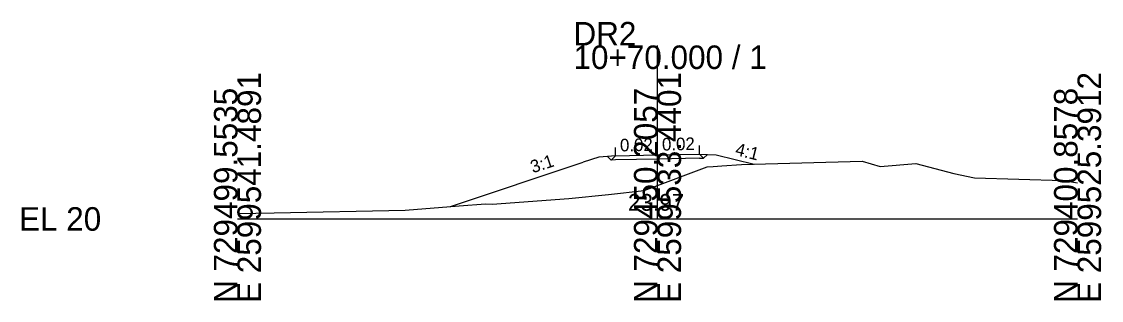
# Model space of a CAD drawing. Extents: x -26 to 1162, y -10 to 9515.
# Drawn here: x -25.7 to 102.8, y 3490.3 to 3523.5 of the extents above; entities that cross this region are included whole.
import ezdxf

# ---------------------------------------------------------------- set-up
doc = ezdxf.new("R2010")
doc.units = 0
for name, color, linetype in [('Exist Cross Section Cell', 7, 'Continuous'), ('Exist XS Center Line Elevation Label', 7, 'Continuous'), ('Exist XS Ground Line', 7, 'Continuous'), ('Prop XS Dump Level', 7, 'Continuous'), ('Prop XS EOT Tick Mark', 7, 'Continuous'), ('Prop XS Finish Grade', 7, 'Continuous'), ('Prop XS Finish Grade Earthwork', 7, 'Continuous'), ('Prop XS Finish Grade Pavement', 7, 'Continuous'), ('Prop XS Pvmt Edge Slope', 7, 'Continuous'), ('Prop XS SE Text', 7, 'Continuous'), ('Prop XS Side Slope Text', 7, 'Continuous'), ('Prop XS Subgrade Earthwork', 7, 'Continuous')]:
    doc.layers.add(name, color=color, linetype=linetype)

msp = doc.modelspace()

# ---------------------------------------------------------------- linework, layer by layer
at = {"layer": 'Exist Cross Section Cell'}
for p, q in [((50, 3500), (50, 3520.64)), ((0, 3500), (50, 3500)), ((50, 3500), (100, 3500))]:
    msp.add_line(p, q, dxfattribs=at)
at = {"layer": 'Exist XS Ground Line'}
msp.add_lwpolyline([(0, 3500.65), (4.38, 3500.72), (19.96, 3501.04), (26.38, 3501.56), (29.53, 3501.79), (30.33, 3501.75), (39.46, 3502.43), (44.16, 3502.9), (48.4, 3503.37), (50, 3503.97), (55.91, 3506.22), (56.63, 3506.25), (57.67, 3506.31), (60, 3506.47), (74.36, 3506.88), (76.5, 3506.25), (80.76, 3506.61), (85.27, 3505.39), (87.73, 3504.9), (98.28, 3504.59), (100, 3504.29)], dxfattribs=at)
at = {"layer": 'Prop XS Dump Level'}
for p, q in [((50, 3507.62), (55, 3507.72)), ((45, 3507.52), (50, 3507.62))]:
    msp.add_line(p, q, dxfattribs=at)
at = {"layer": 'Prop XS EOT Tick Mark'}
for p, q in [((45, 3507.52), (45, 3508.52)), ((55, 3507.72), (55, 3508.72))]:
    msp.add_line(p, q, dxfattribs=at)
at = {"layer": 'Prop XS Finish Grade'}
for p, q in [((55, 3507.72), (55.95, 3507.68)), ((45, 3507.52), (44.05, 3507.44))]:
    msp.add_line(p, q, dxfattribs=at)
at = {"layer": 'Prop XS Finish Grade Earthwork'}
for p, q in [((55.95, 3507.68), (57, 3507.64)), ((25.35, 3501.47), (41.15, 3506.74)), ((43, 3507.36), (41.15, 3506.74)), ((44.05, 3507.44), (43, 3507.36)), ((57, 3507.64), (59.24, 3507.08)), ((59.24, 3507.08), (61.5, 3506.51))]:
    msp.add_line(p, q, dxfattribs=at)
at = {"layer": 'Prop XS Finish Grade Pavement'}
for p, q in [((50, 3507.62), (55, 3507.72)), ((45, 3507.52), (50, 3507.62))]:
    msp.add_line(p, q, dxfattribs=at)
at = {"layer": 'Prop XS Pvmt Edge Slope'}
for p, q in [((55, 3507.72), (55.49, 3507.23)), ((55.49, 3507.23), (55.95, 3507.68)), ((44.49, 3507.01), (44.05, 3507.44)), ((45, 3507.52), (44.49, 3507.01))]:
    msp.add_line(p, q, dxfattribs=at)
at = {"layer": 'Prop XS Subgrade Earthwork'}
for p, q in [((55.49, 3507.23), (55.95, 3507.68)), ((44.49, 3507.01), (44.05, 3507.44)), ((45, 3507.02), (44.49, 3507.01)), ((50, 3507.12), (45, 3507.02)), ((55, 3507.22), (50, 3507.12)), ((55, 3507.22), (55.49, 3507.23))]:
    msp.add_line(p, q, dxfattribs=at)

# ---------------------------------------------------------------- texts
at = {"layer": 'Exist Cross Section Cell'}
for s, p in [('DR2', (40, 3520.64)), ('10+70.000 / 1', (40, 3517.84)), ('EL 20', (-26, 3498.6))]:
    msp.add_text(s, height=2.8, dxfattribs=at).set_placement(p)
for s, p in [('E 2599541.4891', (2.8, 3490)), ('E 2599533.4401', (52.8, 3490)), ('E 2599525.3912', (102.8, 3490)), ('N 729499.5535', (0, 3490)), ('N 729450.2057', (50, 3490)), ('N 729400.8578', (100, 3490))]:
    msp.add_text(s, height=2.8, rotation=90, dxfattribs=at).set_placement(p)
at = {"layer": 'Exist XS Center Line Elevation Label'}
msp.add_text('23.97', height=2, dxfattribs=at).set_placement((46.49, 3500.97))
at = {"layer": 'Prop XS Dump Level'}
for p in [(43, 3507.32), (57, 3507.6)]:
    msp.add_text('Case1', height=0.04, dxfattribs=at).set_placement(p)
at = {"layer": 'Prop XS SE Text'}
for p in [(45.55, 3508.03), (50.55, 3508.13)]:
    msp.add_text('0.02', height=1.5, rotation=1.1458, dxfattribs=at).set_placement(p)
at = {"layer": 'Prop XS Side Slope Text'}
for s, rotation, p in [('4:1', 345.9638, (59.16, 3507.63)), ('3:1', 18.1082, (35.16, 3505.43))]:
    msp.add_text(s, height=1.5, rotation=rotation, dxfattribs=at).set_placement(p)

doc.saveas('drawing.dxf')
